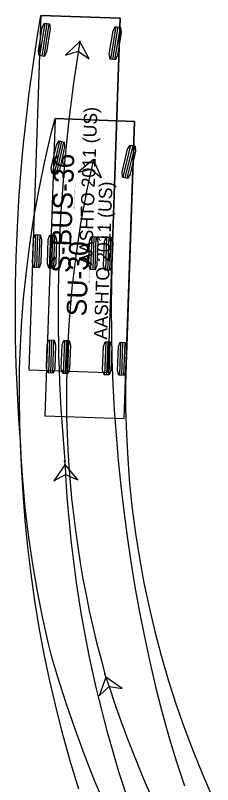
# Model space of a CAD drawing. Extents: x 2096670 to 2098561, y 684033 to 689893.
# Drawn here: x 2097790.8 to 2097810.6, y 688122.5 to 688200.1 of the extents above; entities that cross this region are included whole.
import ezdxf

# ---------------------------------------------------------------- set-up
doc = ezdxf.new("R2010")
doc.units = 0
doc.layers.add('Old_Level_63', color=7, linetype='Continuous')

msp = doc.modelspace()

# ---------------------------------------------------------------- linework, layer by layer
at = {"layer": 'Old_Level_63'}
for p, q in [((2097793.339, 688200.123), (2097792.119, 688164.344)), ((2097801.334, 688199.85), (2097793.339, 688200.123)), ((2097793.339, 688200.123), (2097793.339, 688200.123)), ((2097800.114, 688164.071), (2097801.334, 688199.85)), ((2097793.733, 688199.34), (2097793.205, 688196.049)), ((2097793.939, 688199.307), (2097793.411, 688196.016)), ((2097794.145, 688199.274), (2097793.617, 688195.983)), ((2097800.893, 688198.99), (2097800.35, 688195.702)), ((2097801.099, 688198.956), (2097800.555, 688195.668)), ((2097801.305, 688198.922), (2097800.761, 688195.634)), ((2097794.763, 688189.698), (2097793.724, 688159.716)), ((2097802.758, 688189.422), (2097794.763, 688189.698)), ((2097794.763, 688189.698), (2097794.763, 688189.698)), ((2097801.719, 688159.44), (2097802.758, 688189.422)), ((2097795.216, 688187.436), (2097794.479, 688184.185)), ((2097795.419, 688187.39), (2097794.682, 688184.139)), ((2097795.623, 688187.343), (2097794.885, 688184.093)), ((2097802.377, 688187.025), (2097801.601, 688183.783)), ((2097802.58, 688186.977), (2097801.804, 688183.735)), ((2097802.782, 688186.928), (2097802.007, 688183.686)), ((2097792.793, 688177.995), (2097792.679, 688174.664)), ((2097793.001, 688177.988), (2097792.887, 688174.657)), ((2097793.209, 688177.981), (2097793.095, 688174.65)), ((2097794.292, 688177.944), (2097794.178, 688174.613)), ((2097794.5, 688177.937), (2097794.386, 688174.606)), ((2097794.708, 688177.93), (2097794.595, 688174.598)), ((2097798.456, 688177.802), (2097798.342, 688174.471)), ((2097798.664, 688177.795), (2097798.551, 688174.464)), ((2097798.872, 688177.788), (2097798.759, 688174.456)), ((2097799.955, 688177.751), (2097799.842, 688174.42)), ((2097800.163, 688177.744), (2097800.05, 688174.412)), ((2097800.372, 688177.737), (2097800.258, 688174.405)), ((2097794.198, 688167.371), (2097794.082, 688164.04)), ((2097794.406, 688167.364), (2097794.291, 688164.033)), ((2097794.614, 688167.357), (2097794.499, 688164.026)), ((2097795.697, 688167.319), (2097795.582, 688163.988)), ((2097795.905, 688167.312), (2097795.79, 688163.981)), ((2097796.113, 688167.305), (2097795.998, 688163.974)), ((2097799.861, 688167.175), (2097799.746, 688163.844)), ((2097800.069, 688167.168), (2097799.954, 688163.837)), ((2097800.278, 688167.161), (2097800.162, 688163.829)), ((2097801.36, 688167.123), (2097801.245, 688163.792)), ((2097801.568, 688167.116), (2097801.453, 688163.785)), ((2097801.777, 688167.109), (2097801.661, 688163.777)), ((2097792.119, 688164.344), (2097800.114, 688164.071)), ((2097793.724, 688159.716), (2097801.719, 688159.44))]:
    msp.add_line(p, q, dxfattribs=at)
for points in [[(2097797.142, 688122.009), (2097796.346, 688124.644), (2097795.609, 688127.289), (2097794.927, 688129.953), (2097794.229, 688132.958), (2097793.669, 688135.65), (2097793.168, 688138.346), (2097792.726, 688141.038), (2097792.341, 688143.743), (2097792.014, 688146.455), (2097791.744, 688149.172), (2097791.533, 688151.894), (2097791.379, 688154.619), (2097791.302, 688156.663), (2097791.109, 688159.381), (2097790.958, 688162.101), (2097790.849, 688164.823), (2097790.783, 688167.546), (2097790.761, 688170.265), (2097790.78, 688172.978), (2097790.842, 688175.67), (2097790.964, 688178.745), (2097791.117, 688181.463), (2097791.312, 688184.164), (2097791.549, 688186.861), (2097791.829, 688189.557), (2097792.158, 688192.305), (2097792.536, 688195.084), (2097792.957, 688197.848), (2097793.339, 688200.123), (2097801.334, 688199.85), (2097800.525, 688176.109), (2097800.447, 688173.181), (2097800.422, 688170.598), (2097800.438, 688168.022), (2097800.495, 688165.45), (2097800.591, 688162.88), (2097800.728, 688160.311), (2097800.906, 688157.744), (2097801.124, 688155.181), (2097801.381, 688152.621), (2097801.679, 688150.066), (2097802.017, 688147.516), (2097802.395, 688144.971), (2097802.813, 688142.432), (2097803.271, 688139.898), (2097803.767, 688137.379), (2097804.37, 688134.565), (2097804.952, 688132.092), (2097805.587, 688129.638), (2097806.274, 688127.194), (2097807.012, 688124.771), (2097807.802, 688122.363)], [(2097797.251, 688197.488), (2097795.795, 688196.117), (2097797.091, 688196.501), (2097798.198, 688195.726), (2097797.251, 688197.488)], [(2097799.798, 688120.36), (2097798.74, 688122.909), (2097797.735, 688125.481), (2097796.784, 688128.073), (2097795.888, 688130.686), (2097795.042, 688133.332), (2097794.44, 688135.341), (2097794.105, 688136.698), (2097793.495, 688139.425), (2097792.955, 688142.167), (2097792.485, 688144.923), (2097792.086, 688147.689), (2097791.758, 688150.465), (2097791.501, 688153.248), (2097791.316, 688156.037), (2097791.202, 688158.82), (2097791.159, 688161.602), (2097791.187, 688164.347), (2097791.239, 688166.065), (2097791.381, 688168.836), (2097791.59, 688171.567), (2097791.864, 688174.27), (2097792.207, 688176.971), (2097792.627, 688179.724), (2097793.14, 688182.582), (2097793.724, 688185.408), (2097794.376, 688188.189), (2097794.763, 688189.698), (2097802.758, 688189.422), (2097801.941, 688165.839), (2097801.868, 688162.935), (2097801.873, 688160.394), (2097801.943, 688157.867), (2097802.078, 688155.349), (2097802.276, 688152.835), (2097802.539, 688150.328), (2097802.866, 688147.827), (2097803.257, 688145.336), (2097803.712, 688142.856), (2097804.229, 688140.388), (2097804.81, 688137.934), (2097805.453, 688135.495), (2097806.162, 688133.061), (2097806.934, 688130.643), (2097807.768, 688128.245), (2097808.663, 688125.87), (2097809.619, 688123.519), (2097810.635, 688121.193)], [(2097798.622, 688185.562), (2097797.076, 688184.293), (2097798.395, 688184.588), (2097799.448, 688183.741), (2097798.622, 688185.562)], [(2097795.76, 688154.785), (2097794.617, 688153.144), (2097795.806, 688153.786), (2097797.049, 688153.256), (2097795.76, 688154.785)], [(2097795.76, 688154.785), (2097795.745, 688155.118)], [(2097799.889, 688133.33), (2097799.214, 688131.447), (2097800.195, 688132.378), (2097801.533, 688132.191), (2097799.889, 688133.33)], [(2097799.889, 688133.33), (2097799.788, 688133.647)]]:
    msp.add_lwpolyline(points, dxfattribs=at)
for points in [[(2097793.682, 688199.349), (2097794.196, 688199.266), (2097794.277, 688198.781), (2097793.896, 688196.411), (2097793.668, 688195.975), (2097793.154, 688196.057), (2097793.074, 688196.543), (2097793.454, 688198.913)], [(2097800.842, 688198.999), (2097801.356, 688198.914), (2097801.434, 688198.428), (2097801.042, 688196.06), (2097800.812, 688195.625), (2097800.299, 688195.71), (2097800.22, 688196.196), (2097800.612, 688198.564)], [(2097797.251, 688197.488), (2097795.795, 688196.117), (2097797.091, 688196.501), (2097798.198, 688195.726)], [(2097795.166, 688187.447), (2097795.673, 688187.332), (2097795.723, 688186.842), (2097795.192, 688184.502), (2097794.935, 688184.081), (2097794.428, 688184.196), (2097794.379, 688184.686), (2097794.91, 688187.027)], [(2097802.327, 688187.037), (2097802.832, 688186.916), (2097802.876, 688186.426), (2097802.318, 688184.092), (2097802.057, 688183.674), (2097801.551, 688183.795), (2097801.507, 688184.286), (2097802.066, 688186.62)], [(2097798.622, 688185.562), (2097797.076, 688184.293), (2097798.395, 688184.588), (2097799.448, 688183.741)], [(2097792.741, 688177.997), (2097793.261, 688177.979), (2097793.401, 688177.507), (2097793.32, 688175.109), (2097793.147, 688174.648), (2097792.627, 688174.666), (2097792.487, 688175.137), (2097792.569, 688177.536)], [(2097794.24, 688177.946), (2097794.76, 688177.928), (2097794.901, 688177.456), (2097794.819, 688175.058), (2097794.646, 688174.597), (2097794.127, 688174.614), (2097793.986, 688175.086), (2097794.068, 688177.485)], [(2097798.404, 688177.804), (2097798.924, 688177.786), (2097799.065, 688177.314), (2097798.983, 688174.916), (2097798.81, 688174.455), (2097798.291, 688174.472), (2097798.15, 688174.944), (2097798.232, 688177.343)], [(2097799.904, 688177.753), (2097800.423, 688177.735), (2097800.564, 688177.263), (2097800.482, 688174.865), (2097800.31, 688174.404), (2097799.79, 688174.421), (2097799.649, 688174.893), (2097799.731, 688177.292)], [(2097794.146, 688167.373), (2097794.666, 688167.355), (2097794.806, 688166.883), (2097794.723, 688164.485), (2097794.551, 688164.024), (2097794.031, 688164.042), (2097793.89, 688164.514), (2097793.973, 688166.912)], [(2097795.645, 688167.321), (2097796.165, 688167.303), (2097796.305, 688166.831), (2097796.222, 688164.433), (2097796.05, 688163.972), (2097795.53, 688163.99), (2097795.389, 688164.462), (2097795.473, 688166.86)], [(2097799.809, 688167.177), (2097800.329, 688167.159), (2097800.47, 688166.687), (2097800.387, 688164.289), (2097800.214, 688163.828), (2097799.694, 688163.846), (2097799.554, 688164.317), (2097799.637, 688166.716)], [(2097801.309, 688167.125), (2097801.828, 688167.107), (2097801.969, 688166.635), (2097801.886, 688164.237), (2097801.713, 688163.776), (2097801.193, 688163.794), (2097801.053, 688164.266), (2097801.136, 688166.664)], [(2097795.76, 688154.785), (2097794.617, 688153.144), (2097795.806, 688153.786), (2097797.049, 688153.256)], [(2097799.889, 688133.33), (2097799.214, 688131.447), (2097800.195, 688132.378), (2097801.533, 688132.191)]]:
    msp.add_lwpolyline(points, close=True, dxfattribs=at)
for centre in [(2097797.251, 688197.488), (2097798.622, 688185.562), (2097795.745, 688155.118), (2097795.745, 688155.118), (2097795.76, 688154.785), (2097795.76, 688154.785), (2097799.788, 688133.647), (2097799.788, 688133.647), (2097799.889, 688133.33), (2097799.889, 688133.33)]:
    msp.add_circle(centre, 0.0417, dxfattribs=at)
for centre, radius, start, end in [((2097963.901, 688170.35), 168.845, 170.75111, 185.17613), ((2097900.332, 688161.876), 104.432, 166.89073, 195.68256), ((2097919.779, 688160.491), 124.15, 182.63463, 198.7418), ((2097920.945, 688172.123), 127.12, 197.76821, 209.50363)]:
    msp.add_arc(centre, radius, start, end, dxfattribs=at)

# ---------------------------------------------------------------- texts
for s, height, rotation, p in [('AASHTO 2011 (US)', 1.33333, 88.04695, (2097798.489, 688174.913)), ('S-BUS-36', 2, 88.04695, (2097796.294, 688174.107)), ('(c) 2022 Transoft Solutions, Inc. All rights reserved.', 0.08, 88.04695, (2097796.711, 688180.458)), ('AASHTO 2011 (US)', 1.33333, 88.0164, (2097800, 688167.385)), ('SU-30', 2, 88.0164, (2097797.913, 688169.72)), ('(c) 2022 Transoft Solutions, Inc. All rights reserved.', 0.08, 88.0164, (2097798.224, 688172.931))]:
    msp.add_text(s, height=height, rotation=rotation, dxfattribs=at).set_placement(p)

doc.saveas('drawing.dxf')
